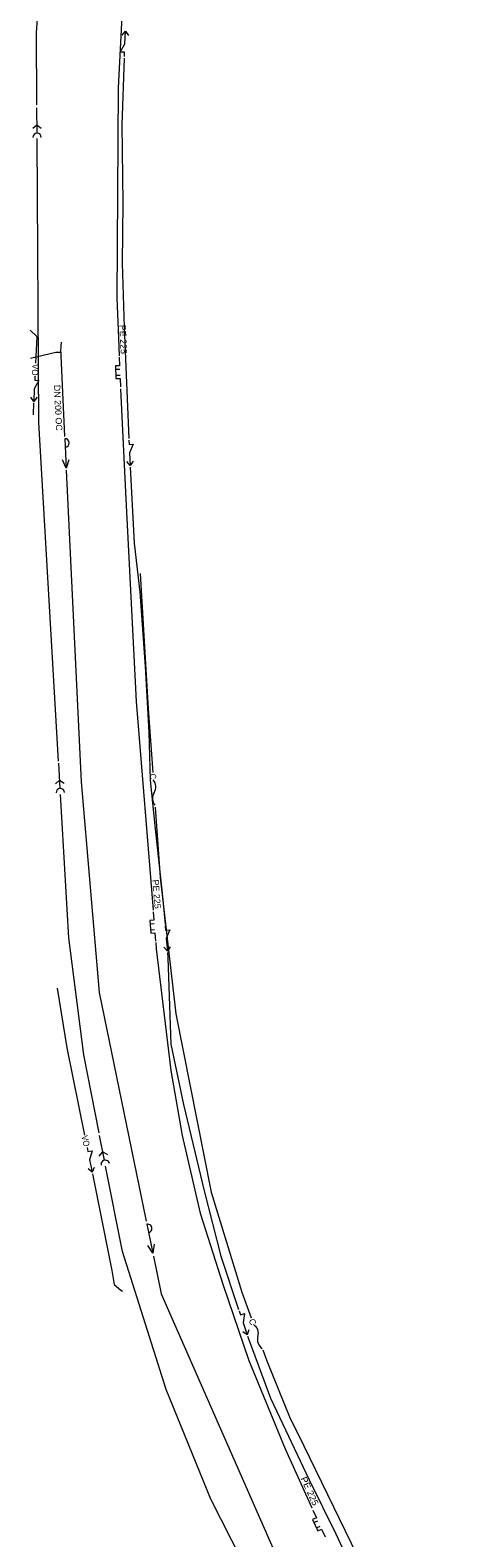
# Model space of a CAD drawing. Extents: x -601552 to -601367, y -1161450 to -1160710.
# Drawn here: x -601552.1 to -601500.7, y -1161262.3 to -1161083.9 of the extents above; entities that cross this region are included whole.
import ezdxf
from ezdxf.enums import TextEntityAlignment as Align

# ---------------------------------------------------------------- set-up
doc = ezdxf.new("R2010")
doc.units = 0
doc.header["$LTSCALE"] = 0.3
for name, color, linetype, lineweight in [('41', 7, 'Continuous', 13), ('50', 7, 'Continuous', 13), ('54', 7, 'Continuous', 13), ('56', 7, 'Continuous', 13), ('57', 7, 'Continuous', 13), ('58', 7, 'Continuous', 13)]:
    doc.layers.add(name, color=color, linetype=linetype, lineweight=lineweight)

msp = doc.modelspace()

# ---------------------------------------------------------------- linework, layer by layer
at = {"layer": '41'}
for p, q in [((-601551.233, -1161096.136), (-601551.253, -1161093.136)), ((-601548.497, -1161173.671), (-601548.671, -1161170.676)), ((-601543.254, -1161217.653), (-601543.833, -1161214.71))]:
    msp.add_line(p, q, dxfattribs=at)
for points in [[(-601551.255, -1161092.771), (-601551.31, -1161084.207), (-601550.128, -1161067.903), (-601548.609, -1161057.251)], [(-601551.737, -1161095.54), (-601551.24, -1161095.136), (-601550.737, -1161095.533)], [(-601548.684, -1161170.454), (-601551.014, -1161130.357), (-601551.23, -1161096.746)], [(-601549.031, -1161173.101), (-601548.555, -1161172.672), (-601548.033, -1161173.043)], [(-601543.894, -1161214.401), (-601545.705, -1161205.201), (-601547.471, -1161191.332), (-601548.456, -1161174.384)], [(-601543.86, -1161217.161), (-601543.447, -1161216.672), (-601542.879, -1161216.968)], [(-601524.465, -1161269.936), (-601530.642, -1161257.748), (-601535.952, -1161244.775), (-601541.124, -1161228.471), (-601543.118, -1161218.344)]]:
    msp.add_lwpolyline(points, dxfattribs=at)
for centre, start, end in [((-601551.2303, -1161096.6363), 0.36748, 180.36748), ((-601548.4682, -1161174.1698), 3.32548, 183.32548), ((-601543.1571, -1161218.1437), 11.137, 191.137)]:
    msp.add_arc(centre, 0.5, start, end, dxfattribs=at)
at = {"layer": '50'}
for p, q in [((-601537.248, -1161175.881), (-601536.66, -1161184.21)), ((-601524.502, -1161240.106), (-601524.04, -1161241.38))]:
    msp.add_line(p, q, dxfattribs=at)
for points in [[(-601539.01, -1161148.23), (-601538.07, -1161164.25), (-601537.539, -1161171.774)], [(-601536.66, -1161184.21), (-601534.79, -1161200.32), (-601530.6, -1161221.42), (-601526.99, -1161233.25), (-601525.882, -1161236.303)], [(-601524.04, -1161241.38), (-601521.24, -1161248.23), (-601520.37, -1161250), (-601505.61, -1161280.23)]]:
    msp.add_lwpolyline(points, dxfattribs=at)
for centre, start, end in [((-601536.3202, -1161174.8286), 147.17084, 220.91063), ((-601538.4209, -1161173.4733), 327.17084, 40.91063), ((-601526.2758, -1161238.1501), 343.07359, 56.81338), ((-601523.8841, -1161238.878), 163.07359, 236.81338)]:
    msp.add_arc(centre, 1.25, start, end, dxfattribs=at)
at = {"layer": '54'}
for p, q in [((-601541.935, -1161124.063), (-601541.435, -1161124.041)), ((-601541.903, -1161124.784), (-601541.403, -1161124.762)), ((-601537.864, -1161189.668), (-601537.365, -1161189.627)), ((-601537.805, -1161190.387), (-601537.307, -1161190.346)), ((-601518.451, -1161260.509), (-601517.996, -1161260.302)), ((-601518.153, -1161261.165), (-601517.698, -1161260.959))]:
    msp.add_line(p, q, dxfattribs=at)
for points in [[(-601532.951, -1161020.626), (-601534.98, -1161032.29), (-601536.45, -1161040.7), (-601539.81, -1161064.45), (-601540.69, -1161073.43), (-601540.83, -1161075.41), (-601541.64, -1161090.76), (-601541.79, -1161115.65), (-601541.6, -1161120.34), (-601541.506, -1161122.464)], [(-601541.497, -1161122.657), (-601541.453, -1161123.656), (-601541.952, -1161123.678), (-601541.886, -1161125.176), (-601541.386, -1161125.154), (-601541.342, -1161126.153)], [(-601541.332, -1161126.366), (-601541.04, -1161132.94), (-601540.73, -1161139.4), (-601539.51, -1161163.37), (-601537.493, -1161188.064)], [(-601537.478, -1161188.246), (-601537.397, -1161189.243), (-601537.895, -1161189.283), (-601537.773, -1161190.778), (-601537.275, -1161190.738), (-601537.193, -1161191.734)], [(-601537.179, -1161191.911), (-601537.12, -1161192.63), (-601535.38, -1161207.04), (-601534.03, -1161214.71), (-601531.93, -1161223.93), (-601529.18, -1161232.44), (-601526.14, -1161241.35), (-601521.86, -1161251.8), (-601518.689, -1161258.777)], [(-601518.57, -1161259.04), (-601518.156, -1161259.951), (-601518.611, -1161260.158), (-601517.99, -1161261.523), (-601517.535, -1161261.316), (-601517.121, -1161262.227)]]:
    msp.add_lwpolyline(points, dxfattribs=at)
at = {"layer": '56'}
for p, q in [((-601552, -1161122.757), (-601549, -1161122.03)), ((-601548.43, -1161122.45), (-601547.969, -1161132.019)), ((-601548.416, -1161122.036), (-601548.37, -1161121.25)), ((-601548.37, -1161121.25), (-601548.342, -1161120.872)), ((-601547.956, -1161132.287), (-601547.787, -1161135.783)), ((-601538.235, -1161225.225), (-601537.529, -1161228.653))]:
    msp.add_line(p, q, dxfattribs=at)
for points in [[(-601548.999, -1161122.027), (-601548.416, -1161122.036), (-601548.43, -1161122.45)], [(-601547.461, -1161134.766), (-601547.787, -1161135.783), (-601548.21, -1161134.802)], [(-601547.777, -1161136.009), (-601546, -1161172.87), (-601543.89, -1161197.79), (-601538.309, -1161224.868)], [(-601537.363, -1161227.598), (-601537.529, -1161228.653), (-601538.098, -1161227.749)], [(-601537.46, -1161228.988), (-601536.54, -1161233.45), (-601518.908, -1161273.557)]]:
    msp.add_lwpolyline(points, dxfattribs=at)
for centre, start, end in [((-601547.9318, -1161132.7864), 272.75924, 92.75924), ((-601538.1344, -1161225.7144), 281.64633, 101.64633)]:
    msp.add_arc(centre, 0.5, start, end, dxfattribs=at)
at = {"layer": '57'}
for points in [[(-601540.891, -1161087.055), (-601540.872, -1161086.556), (-601541.371, -1161086.536), (-601540.833, -1161085.556), (-601540.774, -1161084.058)], [(-601541.168, -1161084.543), (-601540.774, -1161084.058), (-601540.419, -1161084.572)], [(-601540.899, -1161087.255), (-601541.206, -1161095.13), (-601541.057, -1161104.368), (-601541.163, -1161111.528), (-601540.902, -1161119.094), (-601540.355, -1161132.256)], [(-601540.357, -1161132.472), (-601540.333, -1161132.972), (-601539.834, -1161132.948), (-601540.286, -1161133.97), (-601540.214, -1161135.469)], [(-601539.863, -1161134.951), (-601540.214, -1161135.469), (-601540.613, -1161134.987)], [(-601540.206, -1161135.635), (-601539.749, -1161144.661), (-601539.056, -1161150.432), (-601538.448, -1161159.227), (-601537.979, -1161166.993), (-601537.83, -1161172.667), (-601537.257, -1161178.444), (-601536.4, -1161186.054), (-601536.079, -1161189.71)], [(-601536.059, -1161189.932), (-601536.016, -1161190.43), (-601535.518, -1161190.387), (-601535.928, -1161191.427), (-601535.797, -1161192.921)], [(-601535.467, -1161192.39), (-601535.797, -1161192.921), (-601536.214, -1161192.456)], [(-601535.783, -1161193.076), (-601535.729, -1161193.696), (-601535.398, -1161203.908), (-601533.908, -1161211.063), (-601531.461, -1161221.282), (-601529.457, -1161229.025), (-601527.36, -1161235.321)], [(-601527.31, -1161235.472), (-601527.152, -1161235.946), (-601526.678, -1161235.788), (-601526.836, -1161236.895), (-601526.362, -1161238.318)], [(-601526.164, -1161237.725), (-601526.362, -1161238.318), (-601526.876, -1161237.962)], [(-601526.307, -1161238.483), (-601526.246, -1161238.667), (-601523.573, -1161245.819), (-601519.028, -1161255.474), (-601515.871, -1161261.877), (-601512.935, -1161268.121), (-601509.702, -1161274.368), (-601506.556, -1161280.835), (-601502.916, -1161288.08), (-601500.69, -1161292.617)]]:
    msp.add_lwpolyline(points, dxfattribs=at)
at = {"layer": '58'}
for p, q in [((-601551.641, -1161128.03), (-601551.711, -1161129.462)), ((-601548.869, -1161197.301), (-601547.706, -1161204.36)), ((-601547.706, -1161204.36), (-601545.611, -1161214.683))]:
    msp.add_line(p, q, dxfattribs=at)
for points in [[(-601552.052, -1161119.427), (-601551.26, -1161120.2), (-601551.414, -1161123.362)], [(-601551.488, -1161124.874), (-601551.512, -1161125.374), (-601551.012, -1161125.398), (-601551.56, -1161126.373), (-601551.633, -1161127.871)], [(-601551.234, -1161127.39), (-601551.633, -1161127.871), (-601551.984, -1161127.353)], [(-601545.315, -1161216.144), (-601545.215, -1161216.634), (-601544.725, -1161216.535), (-601545.016, -1161217.614), (-601544.718, -1161219.084)], [(-601544.45, -1161218.52), (-601544.718, -1161219.084), (-601545.185, -1161218.669)], [(-601544.681, -1161219.267), (-601542.358, -1161230.715), (-601542.088, -1161232.369), (-601541.319, -1161233.023), (-601541.133, -1161233.154)]]:
    msp.add_lwpolyline(points, dxfattribs=at)

# ---------------------------------------------------------------- texts
at = {"layer": '50', "width": 0.8}
msp.add_text('C', height=0.75, rotation=274.041, dxfattribs=at).set_placement((-601537.8574, -1161172.5792), align=Align.RIGHT)
at = {"layer": '50'}
msp.add_text('C', height=0.75, rotation=289.943, dxfattribs=at).set_placement((-601525.9368, -1161237.2532), align=Align.RIGHT)
at = {"layer": '54'}
for rotation, width, p in [(272.545, 1.05, (-601541.3241, -1161122.2767)), (274.67, 1.05, (-601537.3094, -1161187.9229)), (294.44, 1.1, (-601518.5404, -1161258.6067))]:
    msp.add_text('PE 225', height=0.75, rotation=rotation, dxfattribs=dict(at, width=width)).set_placement(p, align=Align.RIGHT)
at = {"layer": '56', "width": 1.05}
msp.add_text('DN 200 OC', height=0.75, rotation=272.759, dxfattribs=at).set_placement((-601548.9814, -1161131.3659), align=Align.RIGHT)
at = {"layer": '58'}
for rotation, width, p in [(267.214, 0.95, (-601551.8258, -1161124.1088)), (281.471, 0.9, (-601545.8401, -1161215.4434))]:
    msp.add_text('VO', height=0.75, rotation=rotation, dxfattribs=dict(at, width=width)).set_placement(p, align=Align.CENTER)

doc.saveas('drawing.dxf')
